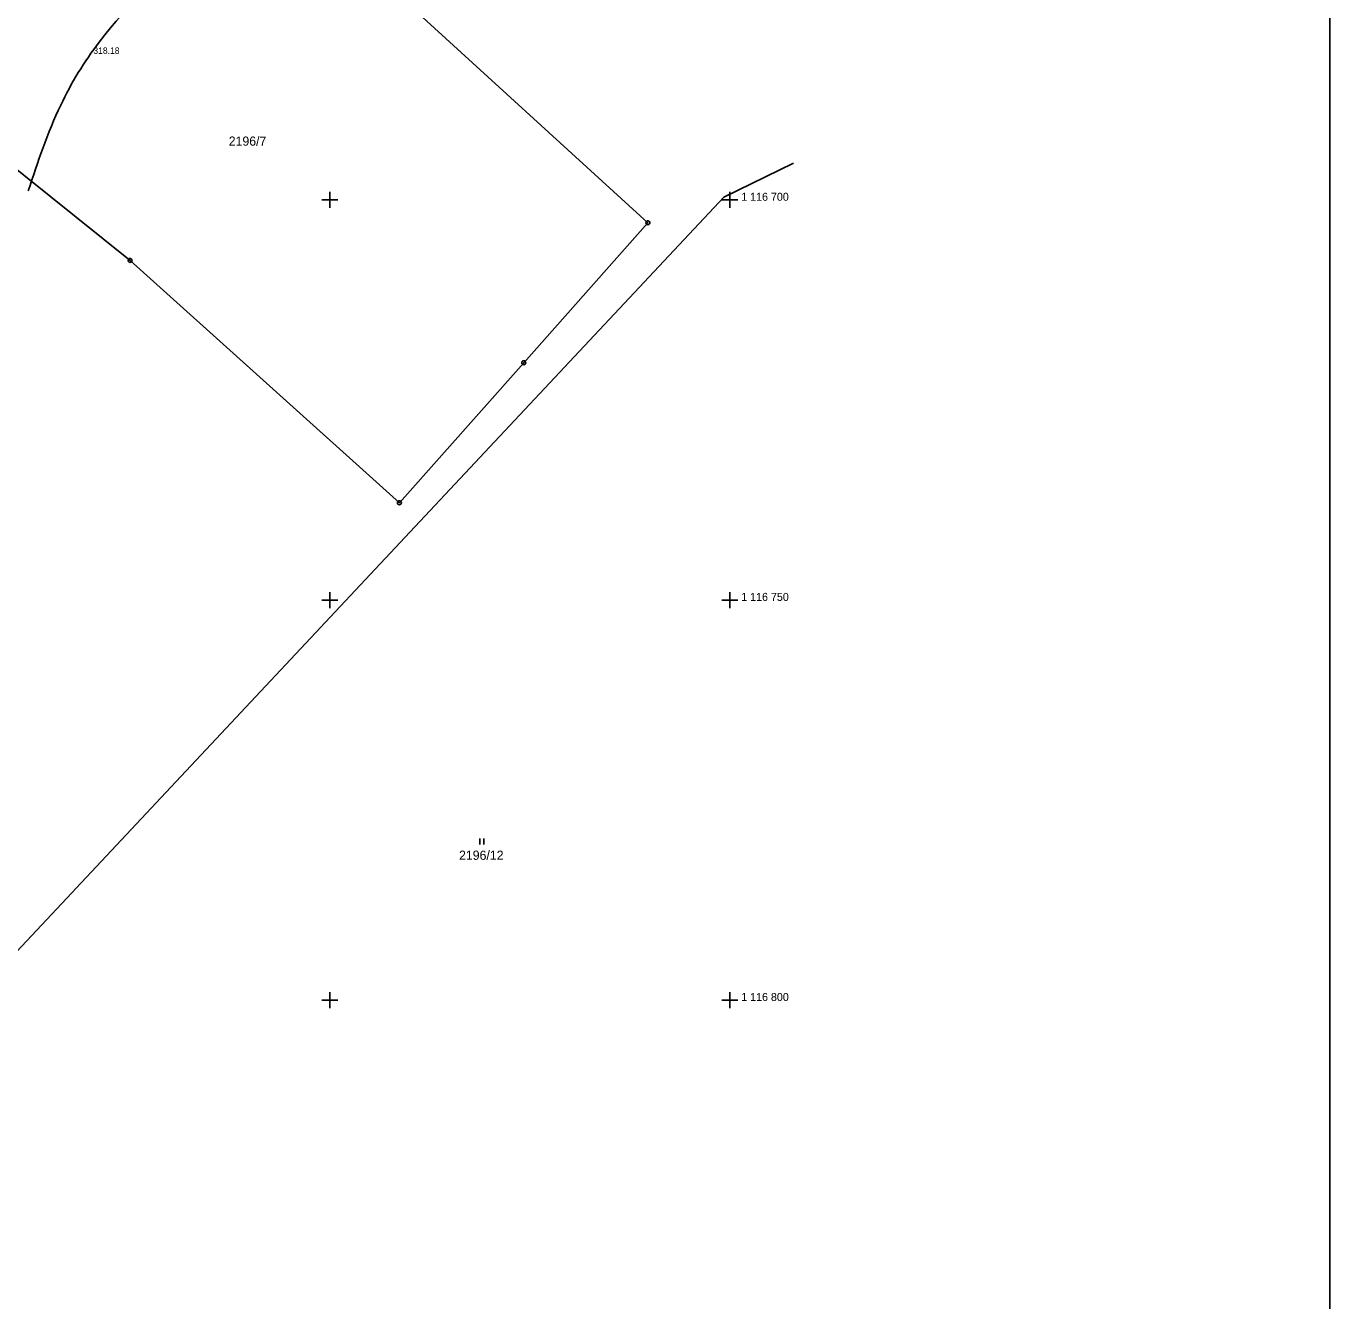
# Model space of a CAD drawing. Extents: x -504375 to -503125, y -1118000 to -1116474.
# Drawn here: x -503288 to -503125, y -1116837.6 to -1116678.3 of the extents above; entities that cross this region are included whole.
import ezdxf

# ---------------------------------------------------------------- set-up
doc = ezdxf.new("R2010")
doc.units = 0
for name, color, linetype in [('Podkladové mapy', 7, 'Continuous'), ('Síť dekadická', 7, 'Continuous'), ('Vrstva 34', 7, 'Continuous'), ('Vrstva 48', 7, 'Continuous'), ('Výšky bodů plotr', 7, 'Continuous')]:
    doc.layers.add(name, color=color, linetype=linetype)

msp = doc.modelspace()

# ---------------------------------------------------------------- linework, layer by layer
at = {"layer": 'Podkladové mapy'}
for p, q in [((-503241.21, -1116674.58), (-503210.25, -1116702.85)), ((-503274.97, -1116707.56), (-503306.69, -1116682.17)), ((-503200.77, -1116699.66), (-503192.069, -1116695.411)), ((-503200.77, -1116699.66), (-503327.64, -1116834.96)), ((-503210.25, -1116702.85), (-503225.76, -1116720.34)), ((-503241.31, -1116737.84), (-503274.97, -1116707.56)), ((-503225.76, -1116720.34), (-503241.31, -1116737.84)), ((-503231.263, -1116780.537), (-503231.263, -1116779.787)), ((-503230.763, -1116779.787), (-503230.763, -1116780.537))]:
    msp.add_line(p, q, dxfattribs=at)
for centre, radius in [((-503210.25, -1116702.85), 0.25), ((-503210.25, -1116702.85), 0.005), ((-503274.97, -1116707.56), 0.25), ((-503274.97, -1116707.56), 0.005), ((-503225.76, -1116720.34), 0.25), ((-503225.76, -1116720.34), 0.005), ((-503241.31, -1116737.84), 0.25), ((-503241.31, -1116737.84), 0.005)]:
    msp.add_circle(centre, radius, dxfattribs=at)
at = {"layer": 'Síť dekadická'}
msp.add_lwpolyline([(-503125, -1116500), (-503125, -1117000), (-503750, -1117000), (-503750, -1116500)], close=True, dxfattribs=at)
at = {"layer": 'Vrstva 34'}
for p, q in [((-503249, -1116700), (-503251, -1116700)), ((-503250, -1116699), (-503250, -1116701)), ((-503199, -1116700), (-503201, -1116700)), ((-503200, -1116699), (-503200, -1116701)), ((-503250, -1116749), (-503250, -1116751)), ((-503200, -1116749), (-503200, -1116751)), ((-503249, -1116750), (-503251, -1116750)), ((-503199, -1116750), (-503201, -1116750)), ((-503250, -1116799), (-503250, -1116801)), ((-503200, -1116799), (-503200, -1116801)), ((-503249, -1116800), (-503251, -1116800)), ((-503199, -1116800), (-503201, -1116800))]:
    msp.add_line(p, q, dxfattribs=at)
at = {"layer": 'Vrstva 48'}
for points in [[(-503228.261, -1116563.145), (-503229.645, -1116567.016), (-503233.265, -1116571.228), (-503245.688, -1116584.541), (-503247.935, -1116586.867), (-503252.973, -1116594.854), (-503254.135, -1116607.338), (-503261.55, -1116616.428), (-503262.857, -1116617.898), (-503273.652, -1116628.941), (-503288.12, -1116641.769), (-503294.834, -1116647.413), (-503299.542, -1116653.756), (-503302.433, -1116657.068), (-503311.897, -1116663.915), (-503313.227, -1116667.667), (-503316.736, -1116674.505), (-503325.627, -1116690.3), (-503328.511, -1116695.009), (-503335.94, -1116707.278), (-503351.034, -1116723.382), (-503365.126, -1116737.245), (-503372.674, -1116748.782), (-503373.925, -1116753.16), (-503378.551, -1116760.666), (-503382.552, -1116767.547), (-503390.579, -1116780.739), (-503398.79, -1116793.818), (-503400.908, -1116797.881), (-503402.495, -1116807.226), (-503404.198, -1116812.046), (-503412.471, -1116822.312), (-503418.387, -1116829.995), (-503420.024, -1116835.788), (-503425.814, -1116843.155), (-503430.336, -1116857.921), (-503433.683, -1116863.223), (-503434.674, -1116865.019), (-503440.926, -1116880.75), (-503445.259, -1116893.88)], [(-503481.504, -1116663.518), (-503468.547, -1116657.036), (-503463.489, -1116655.349), (-503455.413, -1116652.508), (-503447.337, -1116652.508), (-503443.352, -1116653.982), (-503430.298, -1116650.555), (-503416.187, -1116635.106), (-503410.685, -1116628.713), (-503402.504, -1116619.064), (-503381.737, -1116613.158), (-503370.807, -1116610.971), (-503361.189, -1116605.649), (-503353.61, -1116601.494), (-503341.223, -1116596.974), (-503328.544, -1116591.798), (-503324.172, -1116589.392), (-503302.385, -1116583.924), (-503293.932, -1116583.924), (-503286.266, -1116582.08), (-503284.637, -1116580.965), (-503272.933, -1116568.697), (-503269.17, -1116566.723), (-503271.089, -1116569.984), (-503281.636, -1116583.324), (-503281.636, -1116584.01), (-503265.516, -1116590.53), (-503268.945, -1116595.892), (-503268.945, -1116601.682), (-503275.976, -1116612.148), (-503282.064, -1116615.751), (-503283.352, -1116619.8), (-503288.876, -1116631.779), (-503303.377, -1116644.015), (-503307.12, -1116648.093), (-503316.743, -1116659.793), (-503321.087, -1116663.538), (-503326.965, -1116676.097), (-503331.52, -1116684.914), (-503334.134, -1116690.218), (-503342.049, -1116704.413), (-503355.564, -1116718.999), (-503373.009, -1116735.836), (-503382.317, -1116749.959), (-503386.693, -1116758.655), (-503400.779, -1116777.303), (-503409.619, -1116795.183), (-503415, -1116808.93), (-503418.611, -1116811.169), (-503424.106, -1116823.61), (-503426.69, -1116826.983), (-503429.797, -1116836.064), (-503433.946, -1116846.027), (-503439.043, -1116851.839), (-503444.852, -1116860.972), (-503445.916, -1116865.085), (-503449.799, -1116874.02), (-503458.366, -1116891.656), (-503466.054, -1116907.093), (-503467.087, -1116909.659), (-503470.52, -1116921.657)], [(-503228.777, -1116606.86), (-503247.87, -1116624.41), (-503250.03, -1116628.733), (-503254.714, -1116634.261), (-503259.075, -1116640.018), (-503262.555, -1116644.382), (-503263.994, -1116650.649), (-503272.717, -1116660.722), (-503282.634, -1116668.097), (-503288.112, -1116673.922), (-503293.167, -1116682.582), (-503295.386, -1116689.523), (-503299.495, -1116695.666), (-503301.478, -1116696.972), (-503309.455, -1116706.405), (-503311.196, -1116710.807), (-503320.257, -1116722.456), (-503324.189, -1116726.952), (-503334.409, -1116738.528), (-503337.358, -1116741.127), (-503347.86, -1116754.564), (-503355.556, -1116772.228), (-503356.178, -1116773.87), (-503361.611, -1116782.873), (-503368.324, -1116799.361)], [(-503226.376, -1116614.632), (-503233.107, -1116620.885), (-503240.101, -1116634.653), (-503252.255, -1116650.684), (-503264.774, -1116665.135), (-503266.507, -1116667.062), (-503278.833, -1116680.261), (-503283.648, -1116688.161), (-503287.693, -1116698.856)], [(-503265.883, -1116627.544), (-503269.693, -1116631.175), (-503278.458, -1116639.563), (-503288.462, -1116651.097), (-503292.309, -1116656.624), (-503295.894, -1116660.249), (-503304.85, -1116666.159), (-503306.392, -1116672.714), (-503319.808, -1116694.279), (-503329.527, -1116709.34), (-503332.099, -1116712.391), (-503343.962, -1116725.645), (-503346.759, -1116728.532), (-503357.339, -1116738.854), (-503363.022, -1116747.777), (-503365.151, -1116754.165), (-503367.044, -1116758.186), (-503370.891, -1116765.184), (-503373.427, -1116769.471), (-503379.022, -1116778.131), (-503381.668, -1116782.909)]]:
    msp.add_spline(points, degree=3, dxfattribs=at)

# ---------------------------------------------------------------- texts
at = {"layer": 'Podkladové mapy'}
for s, p in [('2196/7', (-503262.64, -1116693.22)), ('2196/12', (-503233.85, -1116782.459))]:
    msp.add_text(s, height=1.15, dxfattribs=at).set_placement(p)
at = {"layer": 'Vrstva 34'}
for s, p in [('1 116 700', (-503198.586, -1116700.102)), ('1 116 750', (-503198.586, -1116750.102)), ('1 116 800', (-503198.586, -1116800.102))]:
    msp.add_text(s, height=1, dxfattribs=at).set_placement(p)
at = {"layer": 'Výšky bodů plotr'}
msp.add_text('318.18 ', height=0.8, dxfattribs=at).set_placement((-503279.56, -1116681.74))

doc.saveas('drawing.dxf')
